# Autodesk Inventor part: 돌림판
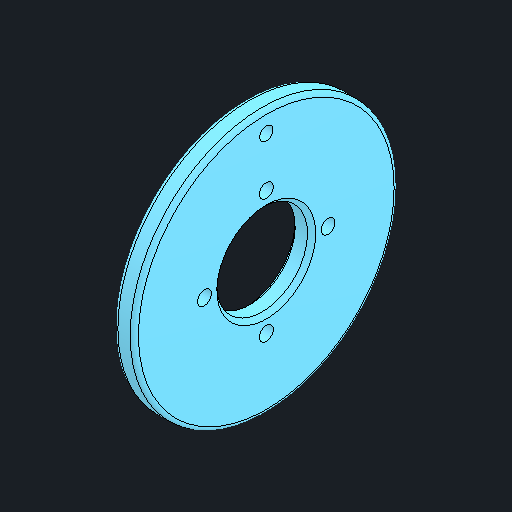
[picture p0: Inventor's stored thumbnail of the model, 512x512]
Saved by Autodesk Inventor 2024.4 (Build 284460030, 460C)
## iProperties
Created: 2026-08
Part Number: 돌림판
Material: 강철, 연강
Document SubType Name: Modeling
Designer: user
Density: 7.85 g/cm^3
Appearance: 기본값
Author: jhkim
Sending System: Autodesk Inventor 2027
Preprocessor: ST-DEVELOPER v20.1
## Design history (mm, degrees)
feature "솔리드1"
node "솔리드2"
